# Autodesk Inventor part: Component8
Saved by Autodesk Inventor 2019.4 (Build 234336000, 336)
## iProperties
Created: 2020-02
Part Number: Component8
Material: Generic
Document SubType Name: Modeling
Designer: Administrator
Density: 1 g/cm^3
Appearance: Default
Title: Component8
Author: Administrator
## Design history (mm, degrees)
feature "Body1"
body "Solid1"
